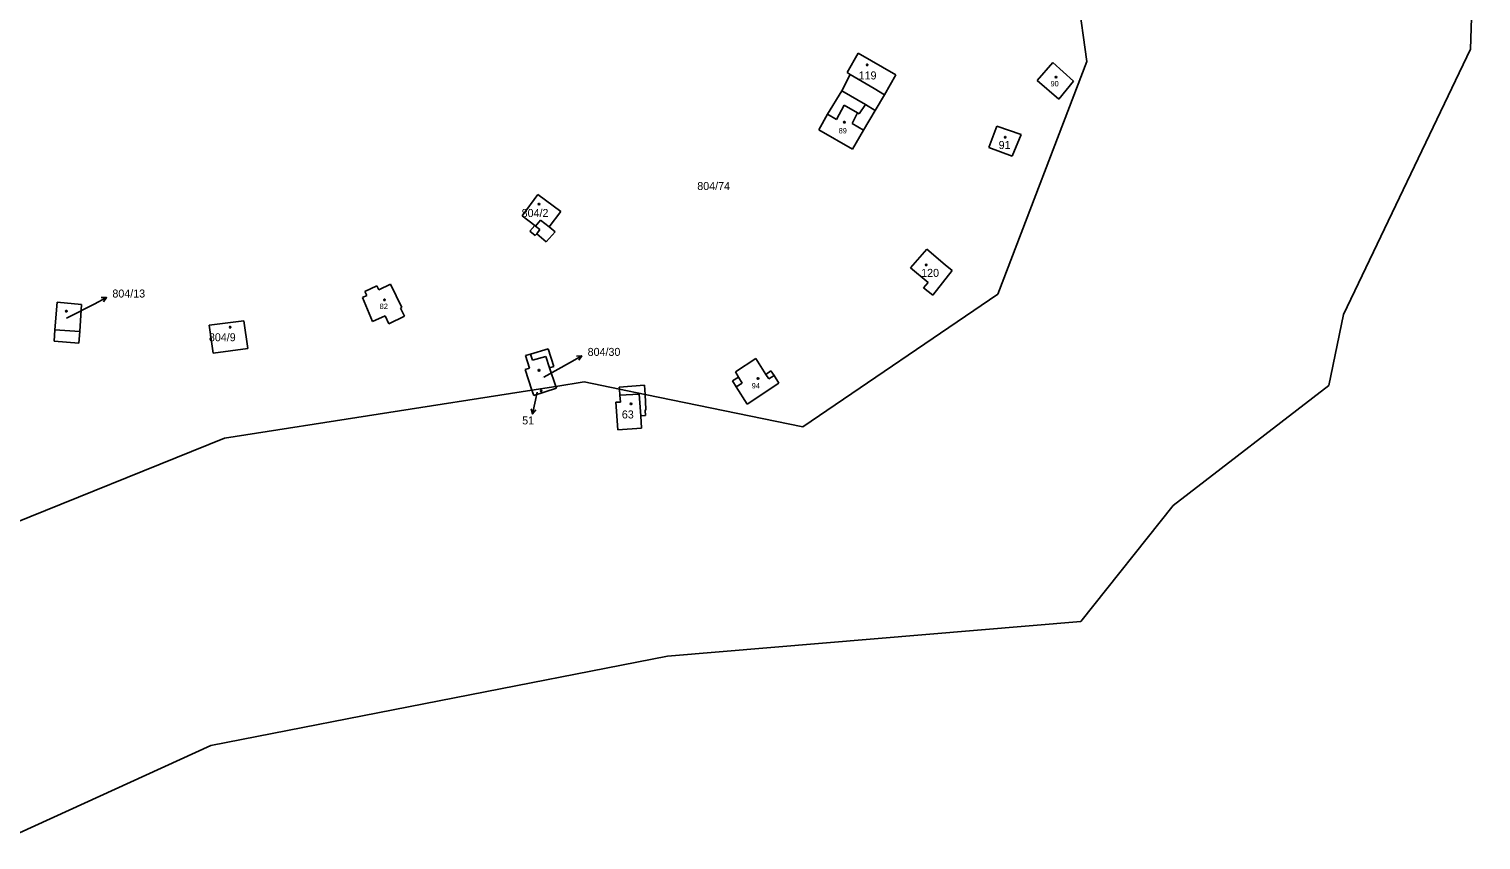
# Model space of a CAD drawing. Extents: x -852001 to -842497, y -1063614 to -1052182.
# Drawn here: x -843033.7 to -842725.2, y -1061954.9 to -1061782.5 of the extents above; entities that cross this region are included whole.
import ezdxf

# ---------------------------------------------------------------- set-up
doc = ezdxf.new("R2010")
doc.units = 0
for name, color, linetype in [('Default', 7, 'Continuous'), ('KN_HRANICE', 7, 'Continuous'), ('KN_KULTURY', 7, 'Continuous'), ('KN_PARCELY', 7, 'Continuous'), ('KN_SLUCKY', 7, 'Continuous')]:
    doc.layers.add(name, color=color, linetype=linetype)

# ---------------------------------------------------------------- blocks, each defined once
blk = doc.blocks.new('10292')
at = {"layer": 'Default'}
blk.add_line((0, 3), (0, 0), dxfattribs=at)
blk.add_lwpolyline([(-0.5, 2), (0, 3), (0.5, 2)], dxfattribs=at)
blk = doc.blocks.new('402')
at = {"layer": 'Default'}
blk.add_lwpolyline([(0.09, 0.15), (0.18, 0), (0.09, -0.15), (-0.09, -0.15), (-0.18, 0), (-0.09, 0.15), (0.09, 0.15)], dxfattribs=at)

msp = doc.modelspace()

# ---------------------------------------------------------------- linework, layer by layer
at = {"layer": 'KN_HRANICE'}
for p, q in [((-842727.42, -1061786.81), (-842725.23, -1061707.32)), ((-842812.56, -1061763.55), (-842809, -1061789.41)), ((-842859.92, -1061791.76), (-842857.53, -1061787.68)), ((-842857.53, -1061787.68), (-842849.58, -1061792.29)), ((-842754.46, -1061843.22), (-842727.42, -1061786.81)), ((-842859.23, -1061792.17), (-842861.06, -1061795.66)), ((-842859.92, -1061791.76), (-842859.23, -1061792.17)), ((-842809, -1061789.41), (-842827.85, -1061838.93)), ((-842816.23, -1061789.64), (-842819.53, -1061793.48)), ((-842811.79, -1061793.62), (-842816.23, -1061789.64)), ((-842849.58, -1061792.29), (-842851.96, -1061796.5)), ((-842819.53, -1061793.48), (-842814.91, -1061797.46)), ((-842814.91, -1061797.46), (-842811.79, -1061793.62)), ((-842864.1, -1061800.63), (-842861.06, -1061795.66)), ((-842856.02, -1061798.6), (-842861.06, -1061795.66)), ((-842853.95, -1061799.81), (-842851.96, -1061796.5)), ((-842865.91, -1061803.94), (-842864.1, -1061800.63)), ((-842856.44, -1061804.05), (-842853.95, -1061799.81)), ((-842853.95, -1061799.81), (-842856.02, -1061798.6)), ((-842865.91, -1061803.94), (-842858.76, -1061808.04)), ((-842858.76, -1061808.04), (-842856.44, -1061804.05)), ((-842828.08, -1061803.14), (-842829.79, -1061807.73)), ((-842822.93, -1061804.98), (-842828.08, -1061803.14)), ((-842822.93, -1061804.98), (-842824.82, -1061809.55)), ((-842824.82, -1061809.55), (-842829.79, -1061807.73)), ((-842925.59, -1061817.74), (-842928.93, -1061822.21)), ((-842920.76, -1061821.35), (-842925.59, -1061817.74)), ((-842928.93, -1061822.21), (-842926.29, -1061824.29)), ((-842920.76, -1061821.35), (-842923.2, -1061824.61)), ((-842926.29, -1061824.29), (-842927.29, -1061825.53)), ((-842927.29, -1061825.53), (-842926.22, -1061826.43)), ((-842926.22, -1061826.43), (-842925.84, -1061826.04)), ((-842923.86, -1061827.76), (-842925.84, -1061826.04)), ((-842921.95, -1061825.61), (-842923.86, -1061827.76)), ((-842923.2, -1061824.61), (-842921.95, -1061825.61)), ((-842842.98, -1061829.35), (-842846.42, -1061833.31)), ((-842842.98, -1061829.35), (-842839.05, -1061832.65)), ((-842846.42, -1061833.31), (-842842.7, -1061836.45)), ((-842837.59, -1061833.85), (-842841.69, -1061839.11)), ((-842839.05, -1061832.65), (-842837.59, -1061833.85)), ((-842959.83, -1061837.13), (-842962.36, -1061838.36)), ((-842962.36, -1061838.36), (-842961.96, -1061839.17)), ((-842959.43, -1061837.94), (-842959.83, -1061837.13)), ((-842956.91, -1061836.77), (-842959.43, -1061837.94)), ((-842954.49, -1061841.75), (-842956.91, -1061836.77)), ((-842842.7, -1061836.45), (-842843.66, -1061837.58)), ((-842841.69, -1061839.11), (-842843.66, -1061837.58)), ((-843028.23, -1061846.45), (-843027.76, -1061840.62)), ((-843027.76, -1061840.62), (-843022.59, -1061841.06)), ((-843022.59, -1061841.06), (-843022.97, -1061846.83)), ((-842961.96, -1061839.17), (-842962.87, -1061839.61)), ((-842962.87, -1061839.61), (-842960.75, -1061844.7)), ((-842827.85, -1061838.93), (-842869.29, -1061867.13)), ((-842995.48, -1061845.52), (-842988.06, -1061844.57)), ((-842988.06, -1061844.57), (-842987.21, -1061850.43)), ((-842960.75, -1061844.7), (-842958.08, -1061843.48)), ((-842957.25, -1061845.18), (-842958.08, -1061843.48)), ((-842953.97, -1061843.57), (-842957.25, -1061845.18)), ((-842954.49, -1061841.75), (-842954.82, -1061841.9)), ((-842954.82, -1061841.9), (-842953.97, -1061843.57)), ((-842757.56, -1061858.35), (-842754.46, -1061843.22)), ((-843028.42, -1061848.92), (-843028.23, -1061846.45)), ((-843022.97, -1061846.83), (-843023.15, -1061849.34)), ((-842994.62, -1061851.42), (-842995.48, -1061845.52)), ((-843023.15, -1061849.34), (-843028.42, -1061848.92)), ((-842987.21, -1061850.43), (-842994.62, -1061851.42)), ((-842927.16, -1061851.63), (-842923.43, -1061850.52)), ((-842922.21, -1061854.25), (-842923.43, -1061850.52)), ((-842928.25, -1061851.95), (-842927.16, -1061851.63)), ((-842927.37, -1061854.6), (-842928.25, -1061851.95)), ((-842883.65, -1061855.4), (-842879.3, -1061852.61)), ((-842879.3, -1061852.61), (-842877.17, -1061855.98)), ((-842928.32, -1061854.92), (-842927.37, -1061854.6)), ((-842926.88, -1061859.29), (-842928.32, -1061854.92)), ((-842922.21, -1061854.25), (-842923.14, -1061854.56)), ((-842923.14, -1061854.56), (-842921.81, -1061858.5)), ((-842884.28, -1061857.33), (-842883, -1061856.51)), ((-842883, -1061856.51), (-842883.65, -1061855.4)), ((-842877.17, -1061855.98), (-842876.1, -1061855.22)), ((-842876.1, -1061855.22), (-842875.44, -1061856.21)), ((-842875.44, -1061856.21), (-842874.41, -1061857.84)), ((-842926.88, -1061859.29), (-842992.2, -1061869.51)), ((-842921.81, -1061858.5), (-842926.88, -1061859.29)), ((-842926.5, -1061860.45), (-842926.88, -1061859.29)), ((-842926.5, -1061860.45), (-842921.69, -1061858.86)), ((-842915.76, -1061857.55), (-842921.81, -1061858.5)), ((-842921.81, -1061858.5), (-842921.69, -1061858.86)), ((-842908.28, -1061859.09), (-842915.76, -1061857.55)), ((-842908.31, -1061858.66), (-842902.96, -1061858.27)), ((-842908.28, -1061859.09), (-842908.31, -1061858.66)), ((-842908.18, -1061860.4), (-842908.28, -1061859.09)), ((-842902.96, -1061858.27), (-842902.85, -1061860.21)), ((-842883.47, -1061858.61), (-842884.28, -1061857.33)), ((-842881.13, -1061862.32), (-842883.47, -1061858.61)), ((-842881.13, -1061862.32), (-842874.41, -1061857.84)), ((-842790.66, -1061883.86), (-842757.56, -1061858.35)), ((-842908.63, -1061867.76), (-842909.07, -1061861.89)), ((-842909.07, -1061861.89), (-842908.07, -1061861.89)), ((-842908.18, -1061860.4), (-842908.07, -1061861.89)), ((-842902.85, -1061860.21), (-842902.66, -1061863.44)), ((-842869.29, -1061867.13), (-842902.85, -1061860.21)), ((-842903.76, -1061864.77), (-842902.74, -1061864.69)), ((-842903.63, -1061867.4), (-842903.76, -1061864.77)), ((-842902.81, -1061863.62), (-842902.66, -1061863.44)), ((-842902.74, -1061864.69), (-842902.81, -1061863.62)), ((-842908.63, -1061867.76), (-842903.63, -1061867.4)), ((-842992.2, -1061869.51), (-843050.58, -1061893.1)), ((-842810.22, -1061908.5), (-842790.66, -1061883.86)), ((-842898.05, -1061915.85), (-842810.22, -1061908.5)), ((-842995.07, -1061934.86), (-842898.05, -1061915.85)), ((-843039.04, -1061954.95), (-842995.07, -1061934.86))]:
    msp.add_line(p, q, dxfattribs=at)
at = {"layer": 'KN_PARCELY'}
for p, q in [((-843025.75, -1061844.03), (-843019.92, -1061841)), ((-842924.32, -1061856.55), (-842918.89, -1061853.49)), ((-842925.75, -1061859.73), (-842926.11, -1061861.44))]:
    msp.add_line(p, q, dxfattribs=at)
at = {"layer": 'KN_SLUCKY'}
for p, q in [((-842859.23, -1061792.17), (-842854.17, -1061795.19)), ((-842854.17, -1061795.19), (-842851.96, -1061796.5)), ((-842864.1, -1061800.63), (-842862.17, -1061801.73)), ((-842862.17, -1061801.73), (-842860.54, -1061798.73)), ((-842857.68, -1061800.37), (-842860.54, -1061798.73)), ((-842857.68, -1061800.37), (-842858.84, -1061802.64)), ((-842857.38, -1061800.54), (-842857.68, -1061800.37)), ((-842856.02, -1061798.6), (-842857.38, -1061800.54)), ((-842858.84, -1061802.64), (-842856.44, -1061804.05)), ((-842926.09, -1061824.45), (-842926.29, -1061824.29)), ((-842925.06, -1061823.14), (-842926.09, -1061824.45)), ((-842925.2, -1061825.15), (-842926.09, -1061824.45)), ((-842925.84, -1061826.04), (-842925.2, -1061825.15)), ((-842923.2, -1061824.61), (-842925.06, -1061823.14)), ((-843022.97, -1061846.83), (-843028.23, -1061846.45)), ((-842926.77, -1061852.95), (-842927.16, -1061851.63)), ((-842923.95, -1061852.15), (-842926.77, -1061852.95)), ((-842923.95, -1061852.15), (-842923.14, -1061854.56)), ((-842883, -1061856.51), (-842882.19, -1061857.8)), ((-842877.17, -1061855.98), (-842876.57, -1061856.92)), ((-842876.57, -1061856.92), (-842875.44, -1061856.21)), ((-842902.85, -1061860.21), (-842908.28, -1061859.09)), ((-842882.19, -1061857.8), (-842883.47, -1061858.61)), ((-842904.07, -1061860.16), (-842908.18, -1061860.4)), ((-842903.76, -1061864.77), (-842904.07, -1061860.16))]:
    msp.add_line(p, q, dxfattribs=at)

# ---------------------------------------------------------------- block references
at = {"layer": 'KN_KULTURY'}
for p in [(-842855.64, -1061790.16), (-842815.53, -1061792.74), (-842860.48, -1061802.35), (-842826.33, -1061805.53), (-842925.39, -1061819.74), (-842843.12, -1061832.68), (-842958.2, -1061840.12), (-843025.79, -1061842.52), (-842990.98, -1061845.91), (-842925.39, -1061855.09), (-842878.83, -1061856.82), (-842924.9, -1061859.45), (-842905.81, -1061862.2)]:
    msp.add_blockref('402', p, dxfattribs=at)
at = {"layer": 'KN_PARCELY'}
for p, rotation in [((-843019.92, -1061841), -62.52031299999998), ((-842918.89, -1061853.49), -60.62955200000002), ((-842926.11, -1061861.44), 168.105817)]:
    msp.add_blockref('10292', p, dxfattribs=dict(at, rotation=rotation))

# ---------------------------------------------------------------- texts
for s, height, p in [('119', 1.7, (-842857.46, -1061793.24)), ('90', 1.14, (-842816.69, -1061794.71)), ('89', 1.14, (-842861.71, -1061804.72)), ('91', 1.7, (-842827.71, -1061808.03)), ('804/74', 1.7, (-842891.74, -1061816.75)), ('804/2', 1.7, (-842929.06, -1061822.49)), ('120', 1.7, (-842844.17, -1061835.22)), ('804/13', 1.7, (-843016.02, -1061839.61)), ('82', 1.14, (-842959.23, -1061842.05)), ('804/13', 0.1, (-843026.04, -1061844.03)), ('804/9', 1.7, (-842995.51, -1061848.91)), ('804/30', 1.7, (-842915.04, -1061852.02)), ('804/30', 0.1, (-842924.61, -1061856.55)), ('51', 0.1, (-842925.83, -1061859.73)), ('94', 1.14, (-842880.18, -1061858.94)), ('51', 1.7, (-842928.95, -1061866.59)), ('63', 1.7, (-842907.77, -1061865.32))]:
    msp.add_text(s, height=height, dxfattribs=at).set_placement(p)

doc.saveas('drawing.dxf')
